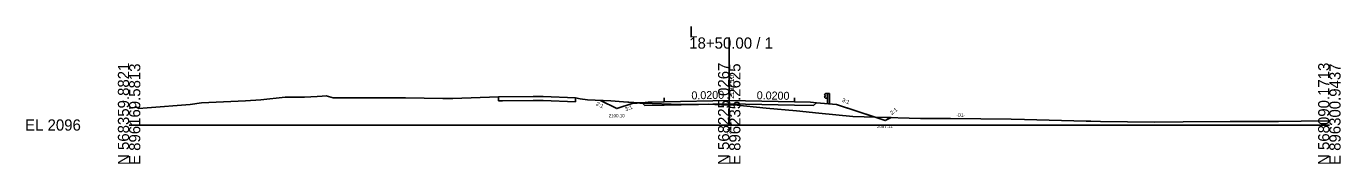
# Model space of a CAD drawing. Extents: x -26 to 1603, y -10 to 13527.
# Drawn here: x -25.7 to 302.8, y 5990.3 to 6024.7 of the extents above; entities that cross this region are included whole.
import ezdxf

# ---------------------------------------------------------------- set-up
doc = ezdxf.new("R2010")
doc.units = 0
for name, color, linetype in [('Default', 7, 'Continuous'), ('Exist XS Center Line Elevation Label', 7, 'Continuous'), ('Exist XS Ground Line', 7, 'Continuous'), ('Old_Level_61', 7, 'Continuous'), ('Old_Level_63', 7, 'Continuous'), ('Prop XS Ditch Slope Text', 7, 'Continuous'), ('Prop XS Ditch Standard Text', 7, 'Continuous'), ('Prop XS Earthwork Shape', 7, 'Continuous'), ('Prop XS EOT Tick Mark', 7, 'Continuous'), ('Prop XS Finish Grade', 7, 'Continuous'), ('Prop XS Finish Grade Earthwork', 7, 'Continuous'), ('Prop XS Finish Grade Paved Shoulder', 7, 'Continuous'), ('Prop XS Finish Grade Pavement', 7, 'Continuous'), ('Prop XS Guardrail', 7, 'Continuous'), ('Prop XS Side Slope Text', 7, 'Continuous'), ('Prop XS Subgrade Earthwork', 7, 'Continuous'), ('Prop XSC Text', 7, 'Continuous')]:
    doc.layers.add(name, color=color, linetype=linetype)

msp = doc.modelspace()

# ---------------------------------------------------------------- linework, layer by layer
at = {"layer": 'Exist XS Ground Line'}
for p, q in [((15.28, 6005.12), (18.11, 6005.59)), ((18.11, 6005.59), (29.12, 6006.06)), ((29.12, 6006.06), (32.89, 6006.28)), ((32.89, 6006.28), (39, 6007.01)), ((39, 6007.01), (43.87, 6006.98)), ((43.87, 6006.98), (47.05, 6007.17)), ((47.05, 6007.17), (48.27, 6007.26)), ((48.27, 6007.26), (49.24, 6007.31)), ((49.24, 6007.31), (49.83, 6007.14)), ((49.83, 6007.14), (51.05, 6006.81)), ((51.05, 6006.81), (54.02, 6006.81)), ((54.02, 6006.81), (57.91, 6006.82)), ((57.91, 6006.82), (60.48, 6006.82)), ((60.48, 6006.82), (69.13, 6006.77)), ((69.13, 6006.77), (78.43, 6006.65)), ((78.43, 6006.65), (79.96, 6006.62)), ((79.96, 6006.62), (80.93, 6006.65)), ((80.93, 6006.65), (92.31, 6007.03)), ((92.31, 6007.03), (100.97, 6007.15)), ((100.97, 6007.15), (102.13, 6007.17)), ((102.13, 6007.17), (103.47, 6007.12)), ((103.47, 6007.12), (111.59, 6006.77)), ((111.59, 6006.77), (112.75, 6006.58)), ((112.75, 6006.58), (114.6, 6006.29)), ((114.6, 6006.29), (120.45, 6006.02)), ((120.45, 6006.02), (123.54, 6005.8)), ((123.54, 6005.8), (127.72, 6005.5)), ((0, 6004.18), (1.88, 6004.49)), ((1.88, 6004.49), (2.44, 6004.13)), ((2.44, 6004.13), (4.55, 6004.34)), ((4.55, 6004.34), (15.28, 6005.12)), ((127.72, 6005.5), (130.71, 6005.38)), ((130.71, 6005.38), (135.49, 6005.18)), ((135.49, 6005.18), (140.01, 6005.12)), ((140.01, 6005.12), (144.74, 6005.19)), ((144.74, 6005.19), (148.08, 6005.08)), ((148.08, 6005.08), (150, 6005.04)), ((150, 6005.04), (151.19, 6005.01)), ((151.19, 6005.01), (159.21, 6004.25)), ((159.21, 6004.25), (166.82, 6003.58)), ((166.82, 6003.58), (172.43, 6003)), ((172.43, 6003), (180.93, 6002.12)), ((180.93, 6002.12), (186.54, 6001.94)), ((186.54, 6001.94), (197.83, 6001.66)), ((197.83, 6001.66), (205.31, 6001.6)), ((205.31, 6001.6), (220.49, 6001.43)), ((220.49, 6001.43), (223.84, 6001.41)), ((223.84, 6001.41), (239.23, 6000.96)), ((239.23, 6000.96), (240.41, 6000.94)), ((240.41, 6000.94), (242.82, 6000.9)), ((242.82, 6000.9), (256.3, 6000.73)), ((256.3, 6000.73), (263.47, 6000.79)), ((263.47, 6000.79), (275.2, 6000.88)), ((275.2, 6000.88), (287.32, 6000.89)), ((287.32, 6000.89), (292.98, 6000.98)), ((292.98, 6000.98), (300, 6001.07))]:
    msp.add_line(p, q, dxfattribs=at)
at = {"layer": 'Old_Level_61'}
for p, q in [((92.31, 6007.03), (92.31, 6006.03)), ((92.31, 6006.03), (93.31, 6006.04)), ((93.31, 6006.04), (100.97, 6006.15)), ((100.97, 6006.15), (102.13, 6006.17)), ((102.13, 6006.17), (103.47, 6006.12)), ((103.47, 6006.12), (111.59, 6005.77)), ((111.59, 6005.77), (111.59, 6006.77))]:
    msp.add_line(p, q, dxfattribs=at)
at = {"layer": 'Old_Level_63'}
for p, q in [((150, 6000), (150, 6021.91)), ((0, 6000), (150, 6000)), ((150, 6000), (300, 6000))]:
    msp.add_line(p, q, dxfattribs=at)
at = {"layer": 'Prop XS Earthwork Shape'}
for points in [[(125.71, 6005.37), (121.89, 6004.1), (117.81, 6006.14), (120.45, 6006.02), (123.54, 6005.8), (127.51, 6005.52)], [(128.22, 6005.57), (127.51, 6005.52), (127.72, 6005.5), (128.31, 6005.48)], [(140.01, 6005.12), (142.33, 6005.15), (133.71, 6004.98), (128.91, 6004.89), (128.31, 6005.48), (130.71, 6005.38), (135.49, 6005.18)], [(166.29, 6004.98), (150, 6005.31), (142.33, 6005.15), (144.74, 6005.19), (148.08, 6005.08), (150, 6005.04), (151.19, 6005.01), (159.21, 6004.25), (166.82, 6003.58), (172.43, 6003), (180.93, 6002.12), (186.48, 6001.94), (176.79, 6005.17), (171.78, 6005.57), (171.1, 6004.89)], [(186.54, 6001.94), (190.45, 6001.84), (188.98, 6001.11), (186.48, 6001.94)]]:
    msp.add_lwpolyline(points, close=True, dxfattribs=at)
at = {"layer": 'Prop XS EOT Tick Mark'}
for p, q in [((133.71, 6005.77), (133.71, 6006.77)), ((166.29, 6005.77), (166.29, 6006.77))]:
    msp.add_line(p, q, dxfattribs=at)
at = {"layer": 'Prop XS Finish Grade'}
for p, q in [((129.71, 6005.69), (128.22, 6005.57)), ((166.29, 6005.77), (170.29, 6005.69)), ((170.29, 6005.69), (171.78, 6005.57))]:
    msp.add_line(p, q, dxfattribs=at)
at = {"layer": 'Prop XS Finish Grade Earthwork'}
for p, q in [((121.89, 6004.1), (117.81, 6006.14)), ((125.71, 6005.37), (121.89, 6004.1)), ((128.22, 6005.57), (125.71, 6005.37)), ((171.78, 6005.57), (176.79, 6005.17)), ((176.79, 6005.17), (188.98, 6001.11)), ((188.98, 6001.11), (190.45, 6001.84))]:
    msp.add_line(p, q, dxfattribs=at)
at = {"layer": 'Prop XS Finish Grade Paved Shoulder'}
msp.add_line((133.71, 6005.77), (129.71, 6005.69), dxfattribs=at)
at = {"layer": 'Prop XS Finish Grade Pavement'}
for p, q in [((133.71, 6005.77), (150, 6006.1)), ((150, 6006.1), (166.29, 6005.77))]:
    msp.add_line(p, q, dxfattribs=at)
at = {"layer": 'Prop XS Guardrail'}
for p, q in [((173.79, 6007.67), (173.76, 6007.61)), ((173.76, 6007.61), (173.79, 6007.55)), ((173.79, 6007.06), (173.76, 6007)), ((173.76, 6007), (173.79, 6006.94)), ((174.08, 6007.87), (173.79, 6007.67)), ((173.79, 6007.55), (174.08, 6007.35)), ((174.08, 6007.26), (173.79, 6007.06)), ((173.79, 6006.94), (174.08, 6006.74)), ((174.58, 6007.87), (174.08, 6007.87)), ((174.08, 6007.35), (174.08, 6007.26)), ((174.08, 6006.74), (174.58, 6006.74)), ((174.58, 6007.87), (174.58, 6005.35)), ((175.08, 6007.87), (174.58, 6007.87)), ((175.08, 6005.31), (175.08, 6007.87))]:
    msp.add_line(p, q, dxfattribs=at)
at = {"layer": 'Prop XS Subgrade Earthwork'}
for p, q in [((128.91, 6004.89), (128.22, 6005.57)), ((133.71, 6004.98), (128.91, 6004.89)), ((150, 6005.31), (133.71, 6004.98)), ((166.29, 6004.98), (150, 6005.31)), ((166.29, 6004.98), (171.1, 6004.89)), ((171.1, 6004.89), (171.78, 6005.57))]:
    msp.add_line(p, q, dxfattribs=at)

# ---------------------------------------------------------------- texts
at = {"layer": 'Default'}
for rotation, p in [(1.1458, (140.57, 6006.41)), (358.8542, (156.86, 6006.46))]:
    msp.add_text('0.0200', height=2, rotation=rotation, dxfattribs=at).set_placement(p)
at = {"layer": 'Exist XS Center Line Elevation Label'}
msp.add_text('2101.04', height=1, rotation=90, dxfattribs=at).set_placement((150.5, 5997.75))
at = {"layer": 'Old_Level_63'}
for s, p in [('18+50.00 / 1', (140, 6019.11)), ('L', (140, 6021.91)), ('EL 2096', (-26, 5998.6))]:
    msp.add_text(s, height=2.8, dxfattribs=at).set_placement(p)
for s, p in [('N 568090.1713', (300, 5990)), ('N 568359.8821', (0, 5990)), ('E 896169.5813', (2.8, 5990)), ('N 568225.0267', (150, 5990)), ('E 896235.2625', (152.8, 5990)), ('E 896300.9437', (302.8, 5990))]:
    msp.add_text(s, height=2.8, rotation=90, dxfattribs=at).set_placement(p)
at = {"layer": 'Prop XS Ditch Slope Text'}
msp.add_text('3:1', height=1, rotation=22.6274, dxfattribs=at).set_placement((124.18, 6003.39))
at = {"layer": 'Prop XS Ditch Standard Text'}
for s, p in [('2100.10', (119.87, 6001.95)), ('-D1-', (206.79, 6002.13)), ('2097.11', (186.92, 5999.23))]:
    msp.add_text(s, height=0.8, dxfattribs=at).set_placement(p)
at = {"layer": 'Prop XS Side Slope Text'}
for s, rotation, p in [('2:1', 333.4351, (116.61, 6005.01)), ('3:1', 338.821, (178.08, 6005.86)), ('2:1', 37.5433, (190.65, 6002.47))]:
    msp.add_text(s, height=1, rotation=rotation, dxfattribs=at).set_placement(p)
at = {"layer": 'Prop XSC Text'}
msp.add_text(' 2102.10', height=1.2, rotation=90, dxfattribs=at).set_placement((151.2, 6006.1))

doc.saveas('drawing.dxf')
